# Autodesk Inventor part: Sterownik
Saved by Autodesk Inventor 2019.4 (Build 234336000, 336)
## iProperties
Created: 2020-01
Part Number: Sterownik
Material: Generic
Document SubType Name: Modeling
Designer: Administrator
Density: 1 g/cm^3
Appearance: Default
Title: Sterownik v3
Author: Administrator
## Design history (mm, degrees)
feature "Body1"
feature "Body2"
feature "Body3"
body "Solid1"
body "Solid2"
body "Solid3"
